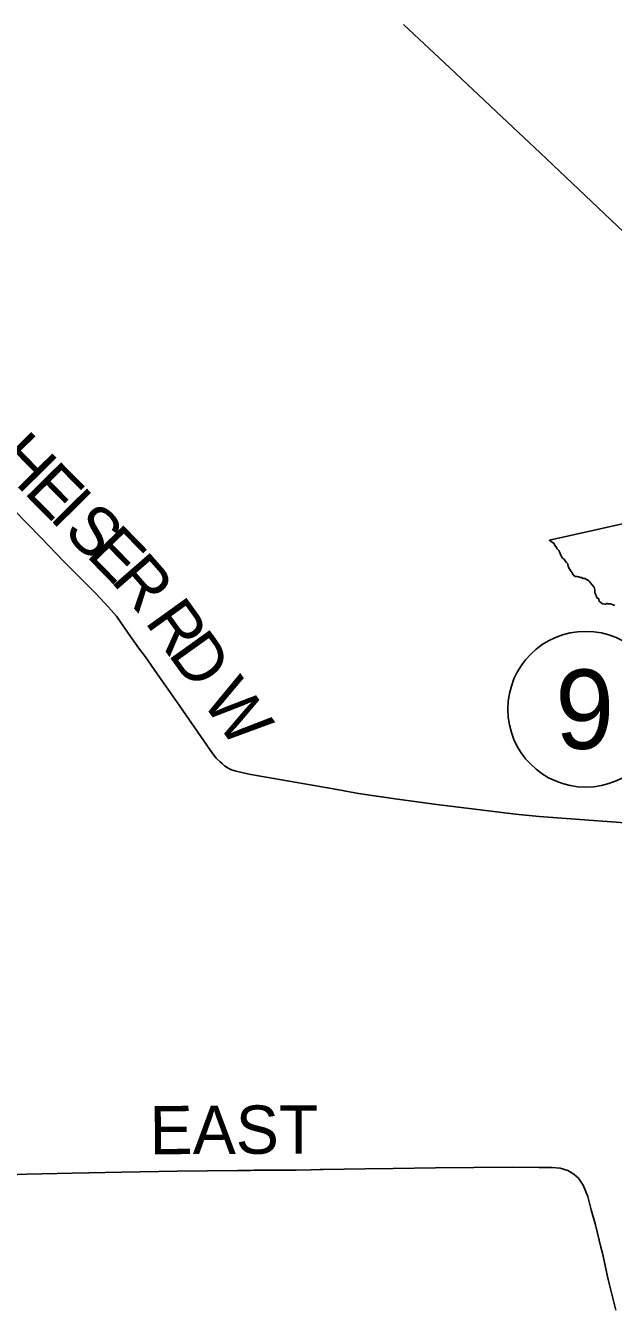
# Model space of a CAD drawing. Extents: x 40529 to 41139, y 15164 to 15584.
# Drawn here: x 40618.21 to 40638.96, y 15438.42 to 15483.78 of the extents above; entities that cross this region are included whole.
import ezdxf

# ---------------------------------------------------------------- set-up
doc = ezdxf.new("R2010")
doc.units = 0
for name, color, linetype in [('GM_X_Corporation', 7, 'Continuous'), ('GM_X_State_Route', 7, 'Continuous'), ('GM_X_Township_Road', 7, 'Continuous'), ('GM_X_Township_Road_Text', 7, 'Continuous'), ('SH_Data', 7, 'Continuous'), ('SH_Text', 7, 'Continuous')]:
    doc.layers.add(name, color=color, linetype=linetype)

msp = doc.modelspace()

# ---------------------------------------------------------------- linework, layer by layer
at = {"layer": 'GM_X_Corporation'}
msp.add_lwpolyline([(40639.009, 15463.305), (40638.917, 15463.338), (40638.858, 15463.362), (40638.839, 15463.371), (40638.82, 15463.37), (40638.752, 15463.373), (40638.747, 15463.377), (40638.745, 15463.376), (40638.666, 15463.351), (40638.575, 15463.372), (40638.452, 15463.456), (40638.442, 15463.526), (40638.443, 15463.547), (40638.373, 15463.584), (40638.349, 15463.657), (40638.3, 15463.751), (40638.301, 15463.856), (40638.294, 15463.907), (40638.282, 15463.954), (40638.269, 15463.97), (40638.202, 15464.048), (40638.154, 15464.109), (40638.114, 15464.155), (40638.089, 15464.181), (40638.043, 15464.219), (40638.013, 15464.232), (40637.959, 15464.259), (40637.895, 15464.26), (40637.828, 15464.293), (40637.795, 15464.3), (40637.733, 15464.319), (40637.682, 15464.328), (40637.605, 15464.337), (40637.535, 15464.394), (40637.507, 15464.445), (40637.492, 15464.48), (40637.474, 15464.509), (40637.4, 15464.611), (40637.36, 15464.695), (40637.354, 15464.751), (40637.351, 15464.769), (40637.348, 15464.776), (40637.33, 15464.801), (40637.303, 15464.832), (40637.262, 15464.885), (40637.222, 15464.944), (40637.203, 15464.961), (40637.167, 15464.979), (40637.126, 15465.036), (40637.102, 15465.081), (40637.058, 15465.202), (40637.044, 15465.23), (40637.031, 15465.249), (40637.012, 15465.271), (40636.978, 15465.311), (40636.953, 15465.351), (40636.892, 15465.436), (40636.873, 15465.475), (40636.873, 15465.488), (40636.863, 15465.492), (40636.81, 15465.533), (40636.76, 15465.565), (40636.703, 15465.612), (40641.064, 15466.592)], dxfattribs=at)
at = {"layer": 'GM_X_State_Route'}
msp.add_lwpolyline([(40631.547, 15483.816), (40633.184, 15482.292), (40635.219, 15480.375), (40636.374, 15479.292), (40639.551, 15476.277), (40640.161, 15475.701), (40640.758, 15475.114), (40641.268, 15474.603)], dxfattribs=at)
at = {"layer": 'GM_X_Township_Road'}
for points in [[(40617.776, 15466.702), (40618.761, 15465.697), (40619.54, 15464.875), (40620.686, 15463.73), (40621.13, 15463.252), (40621.411, 15462.926), (40621.823, 15462.337), (40622.192, 15461.813), (40622.422, 15461.503), (40622.855, 15460.896), (40623.55, 15459.902), (40624.389, 15458.68), (40624.821, 15458.069), (40624.939, 15457.922), (40625.07, 15457.786), (40625.142, 15457.724), (40625.229, 15457.643), (40625.358, 15457.564), (40625.481, 15457.51), (40625.641, 15457.459), (40625.886, 15457.401), (40626.162, 15457.347), (40629.131, 15456.818), (40629.958, 15456.675), (40631.342, 15456.47), (40632.728, 15456.278), (40635.505, 15455.941), (40636.341, 15455.858), (40637.457, 15455.78), (40639.689, 15455.612)], [(40616.955, 15443.181), (40618.248, 15443.235), (40619.846, 15443.264), (40621.604, 15443.304), (40623.563, 15443.334), (40625.698, 15443.36), (40626.161, 15443.36), (40626.261, 15443.369), (40627.756, 15443.373), (40628.291, 15443.387), (40628.606, 15443.391), (40628.71, 15443.392), (40630.198, 15443.418), (40631.186, 15443.436), (40632.681, 15443.459), (40635.382, 15443.476), (40636.334, 15443.466), (40636.789, 15443.466), (40637.082, 15443.439), (40637.353, 15443.361), (40637.567, 15443.234), (40637.725, 15443.085), (40637.895, 15442.845), (40638.052, 15442.442), (40638.175, 15441.97), (40638.327, 15441.437), (40638.52, 15440.649), (40638.577, 15440.444), (40638.778, 15439.508), (40639.05, 15438.423)]]:
    msp.add_lwpolyline(points, dxfattribs=at)
at = {"layer": 'SH_Data'}
msp.add_lwpolyline([(40631.547, 15483.816), (40633.184, 15482.292), (40635.219, 15480.375), (40636.374, 15479.292), (40639.551, 15476.277)], dxfattribs=at)
at = {"layer": 'SH_Text'}
msp.add_circle((40637.983, 15459.646), 2.75, dxfattribs=at)

# ---------------------------------------------------------------- texts
at = {"layer": 'GM_X_Township_Road_Text'}
for s, height, rotation, p in [('H', 1.706, 314.6457, (40617.057, 15468.366)), ('E', 1.706, 314.6273, (40618.112, 15467.297)), ('I', 1.706, 314.6247, (40619.008, 15466.389)), ('S', 1.706, 314.6203, (40619.501, 15465.89)), ('E', 1.706, 314.3394, (40620.308, 15465.072)), ('R', 1.706, 311.078, (40621.182, 15464.178)), ('R', 1.706, 305.7278, (40622.391, 15462.734)), ('D', 1.706, 305.5817, (40623.209, 15461.597)), ('W', 1.706, 305.347, (40624.387, 15459.95)), ('EAST', 1.7063, 0.2753, (40622.587, 15443.931))]:
    msp.add_text(s, height=height, rotation=rotation, dxfattribs=at).set_placement(p)
at = {"layer": 'SH_Text'}
msp.add_text('9', height=2.8, dxfattribs=at).set_placement((40636.905, 15458.246))

doc.saveas('drawing.dxf')
